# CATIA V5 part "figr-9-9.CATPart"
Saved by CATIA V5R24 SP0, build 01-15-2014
Part number: Part1
Bounding box of the stored display mesh (mm): x -15.705 to 88.369, y 0 to 286.83, z -20.723 to 20.723
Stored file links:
  D:\KAVITA\CATIA V5-6R2014 Project_ Kavita\CATIA V5-6R2014_partfiles\Partfiles\c09_catia_v5-6r2014_prt\figr-9-9.CATPart
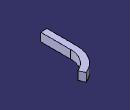
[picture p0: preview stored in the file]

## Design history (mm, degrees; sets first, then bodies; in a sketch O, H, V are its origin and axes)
Body1 (main body)
  Sketch1 on xy-plane, origin (0, 0, 0), H (1, 0, 0), V (0, 1, 0)
    line L1 (0, 0) -> (0, 150)
    arc A1 centre (131.8599, 150) radius 131.8599 from (0, 150) to (82.4884, 272.2681) cw
    length L1 = 150
    tangency: A1 L1
  Sketch2 on zx-plane, origin (0, 0, 0), H (-1, 0, 0), V (0, 0, 1)
    line L1 (15.7048, 20.7231) -> (15.7048, -20.7231)
    line L2 (15.7048, -20.7231) -> (-15.7048, -20.7231)
    line L3 (-15.7048, -20.7231) -> (-15.7048, 20.7231)
    line L4 (-15.7048, 20.7231) -> (15.7048, 20.7231)
    vertical: L1 V, L3 V
    horizontal: L2 H, L4 H
    equidistance: L1 L3 O, L2 L4 O
  Rib1: profile Sketch2, centre curve Sketch1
